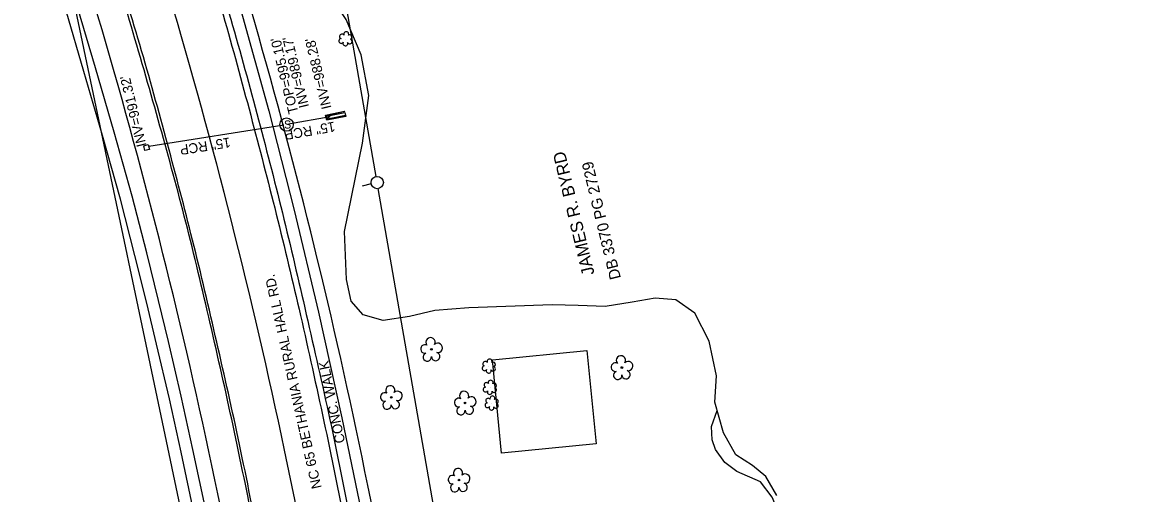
# Model space of a CAD drawing. Extents: x 1611576 to 1617186, y 899279 to 905462.
# Drawn here: x 1616538.9 to 1616993.3, y 902658.3 to 902848.6 of the extents above; entities that cross this region are included whole.
import ezdxf

# ---------------------------------------------------------------- set-up
doc = ezdxf.new("R2010")
doc.units = 0
for name, color, linetype in [('Default', 7, 'Continuous'), ('Exist Building', 7, 'Continuous'), ('Exist Horizontal Alignment', 7, 'Continuous'), ('Exist Property Deed Book Text', 7, 'Continuous'), ('Exist Property Owner Text', 7, 'Continuous'), ('Exist Right of Way Line', 7, 'Continuous'), ('Exist Roads Curbs', 7, 'Continuous'), ('Exist Roads EOP', 7, 'Continuous'), ('Exist Roads EOP Other', 7, 'Continuous'), ('Exist Roads EOP Other Text', 7, 'Continuous'), ('Exist Roads EOP Text', 7, 'Continuous'), ('Exist Roads EOT', 7, 'Continuous'), ('Exist Structure Minor Drop Inlet', 7, 'Continuous'), ('Exist Structure Minor Head and End Wall', 7, 'Continuous'), ('Exist Structure Minor Pipes RCP 15 Inch', 7, 'Continuous'), ('Exist Structure Minor Pipes RCP 15 Inch Invert', 7, 'Continuous'), ('Exist Structure Minor Pipes RCP 15 Inch Text', 7, 'Continuous'), ('Exist Structure Minor Storm Sewer Manhole CELL', 7, 'Continuous'), ('Exist Structure Minor Storm Sewer Manhole Top Elevation', 7, 'Continuous'), ('Exist Vegetation Hedge Row', 7, 'Continuous'), ('Exist Vegetation Shrub CELL', 7, 'Continuous'), ('Exist Vegetation Tree CELL', 7, 'Continuous'), ('Exist Vegetation Woods Line', 7, 'Continuous'), ('Prop OH Pow Lines', 7, 'Continuous')]:
    doc.layers.add(name, color=color, linetype=linetype)

# ---------------------------------------------------------------- blocks, each defined once
blk = doc.blocks.new('EXIST STRUCTURE MINOR STORM SEWER MANHOLE')
at = {"layer": 'Exist Structure Minor Storm Sewer Manhole CELL'}
blk.add_circle((0, 0), 0.0539, dxfattribs=at)
blk.add_text('S', height=0.065, dxfattribs=at).set_placement((-0.0206, -0.032))

msp = doc.modelspace()

# ---------------------------------------------------------------- linework, layer by layer
at = {"layer": 'Default'}
msp.add_line((1616679.58, 902783.35), (1616675.92, 902782.51), dxfattribs=at)
msp.add_circle((1616682.02, 902783.91), 2.5, dxfattribs=at)
at = {"layer": 'Exist Building'}
msp.add_lwpolyline([(1616766.61, 902716.05), (1616770.33, 902678.38), (1616732.23, 902674.63), (1616728.52, 902712.29)], close=True, dxfattribs=at)
at = {"layer": 'Exist Horizontal Alignment'}
msp.add_arc((1614325.74, 902186.35), 2370, 9.05, 18.23333, dxfattribs=at)
at = {"layer": 'Exist Right of Way Line'}
msp.add_line((1616010.65, 905462.23), (1616993.32, 900797.76), dxfattribs=at)
for radius, end in [(2400, 17.96643), (2340, 18.2273)]:
    msp.add_arc((1614325.74, 902186.35), radius, 9.05, end, dxfattribs=at)
at = {"layer": 'Exist Roads Curbs'}
msp.add_spline([(1616609.89, 902892.41), (1616622.17, 902852.43), (1616633.45, 902811.75), (1616643.74, 902771.73), (1616653.39, 902730.67), (1616662.94, 902688.03), (1616671.61, 902645.14)], degree=3, dxfattribs=at)
at = {"layer": 'Exist Roads EOP'}
for points in [[(1616664.02, 902435.24), (1616659.23, 902479.02), (1616653.86, 902521.19), (1616647.48, 902561.19), (1616640.05, 902603.13), (1616633.52, 902638.17), (1616624.95, 902680.56), (1616615.82, 902721.84), (1616606.01, 902763.05), (1616595.75, 902801.7), (1616584.26, 902841.93), (1616572.3, 902881.24), (1616564.26, 902906.37), (1616556.43, 902931.12), (1616543.99, 902967.9), (1616530.08, 903008.97), (1616517.05, 903047.39)], [(1616607.54, 902891.47), (1616619.8, 902851.65), (1616630.95, 902811.11), (1616641.26, 902771.18), (1616651.06, 902730.14), (1616660.51, 902687.43), (1616669.23, 902644.79), (1616673.27, 902623.83), (1616676.02, 902609.12), (1616683.43, 902567.11), (1616690.02, 902525.73), (1616695.57, 902482.82), (1616700.47, 902437.88)]]:
    msp.add_spline(points, degree=3, dxfattribs=at)
at = {"layer": 'Exist Roads EOP Other'}
for points in [[(1616614.65, 902893.86), (1616626.96, 902853.56), (1616638.24, 902812.83), (1616648.55, 902772.75), (1616658.26, 902731.61), (1616667.73, 902688.88), (1616676.31, 902647.23)], [(1616588.99, 902755.56), (1616583.12, 902778.42), (1616575.83, 902804.32), (1616568.31, 902830.2), (1616561.1, 902854.77), (1616553.97, 902877.13), (1616549.79, 902889.69), (1616545.16, 902888.13)], [(1616584.24, 902754.42), (1616578.41, 902777.13), (1616571.14, 902802.96), (1616563.63, 902828.8), (1616556.43, 902853.31), (1616549.33, 902875.6), (1616545.16, 902888.13)], [(1616669.29, 902810.95), (1616662.67, 902809.69), (1616662.27, 902810.92), (1616668.94, 902812.24), (1616669.29, 902810.95)], [(1616648.51, 902316.11), (1616647.25, 902342.52), (1616646.14, 902367.57), (1616644.85, 902387.63), (1616643.4, 902403.89), (1616641.55, 902422), (1616639.65, 902441.45), (1616637.53, 902461.4), (1616635.2, 902482.65), (1616632, 902508.68), (1616628.75, 902531.69), (1616625.18, 902554.85), (1616621.17, 902580.26), (1616616.86, 902604.66), (1616612.24, 902629.12), (1616608.13, 902650.05), (1616602.88, 902675.06), (1616598.15, 902696.53), (1616592.96, 902718.62), (1616589.01, 902735.14), (1616584.24, 902754.42)], [(1616653.39, 902316.3), (1616652.13, 902342.73), (1616651.02, 902367.82), (1616649.72, 902387.98), (1616648.26, 902404.34), (1616646.41, 902422.47), (1616644.51, 902441.92), (1616642.39, 902461.9), (1616640.05, 902483.2), (1616636.84, 902509.29), (1616633.58, 902532.38), (1616630.01, 902555.58), (1616625.98, 902581.04), (1616621.66, 902605.52), (1616617.03, 902630.01), (1616612.92, 902650.99), (1616607.66, 902676.06), (1616602.92, 902697.58), (1616597.72, 902719.72), (1616593.76, 902736.26), (1616588.99, 902755.56)]]:
    msp.add_lwpolyline(points, dxfattribs=at)
at = {"layer": 'Exist Roads EOT'}
msp.add_spline([(1616665.13, 902435.43), (1616660.48, 902479.08), (1616654.89, 902521.26), (1616648.51, 902561.33), (1616641.12, 902603.28), (1616634.46, 902638.28), (1616625.9, 902680.69), (1616616.67, 902721.99), (1616606.86, 902763.22), (1616596.71, 902801.99), (1616585.45, 902842.18), (1616573.19, 902881.5), (1616565.19, 902906.61), (1616557.25, 902931.31), (1616544.89, 902968.22), (1616530.94, 903009.35), (1616518.06, 903047.65)], degree=3, dxfattribs=at)
at = {"layer": 'Exist Structure Minor Drop Inlet'}
msp.add_lwpolyline([(1616590.07, 902797.3), (1616588.28, 902796.82), (1616587.76, 902798.76), (1616589.55, 902799.24)], close=True, dxfattribs=at)
at = {"layer": 'Exist Structure Minor Head and End Wall'}
msp.add_lwpolyline([(1616669.36, 902810.59), (1616661.68, 902809.13), (1616661.19, 902811.17), (1616668.87, 902812.75), (1616668.95, 902812.54), (1616661.48, 902810.88), (1616662, 902809.48), (1616669.32, 902810.85), (1616669.36, 902810.59)], dxfattribs=at)
at = {"layer": 'Exist Structure Minor Pipes RCP 15 Inch'}
for p, q in [((1616644.38, 902807.05), (1616589.89, 902798.47)), ((1616644.38, 902807.05), (1616589.89, 902798.47)), ((1616663.03, 902810.45), (1616646.24, 902807.53)), ((1616663.03, 902810.45), (1616646.24, 902807.53))]:
    msp.add_line(p, q, dxfattribs=at)
at = {"layer": 'Exist Vegetation Hedge Row'}
msp.add_lwpolyline([(1616844.72, 902649.14), (1616841.43, 902656.84), (1616836.76, 902662.96), (1616827.16, 902667.24), (1616822.29, 902670.83), (1616818.54, 902676.14), (1616817.17, 902680.02), (1616816.97, 902685.34), (1616819.21, 902691.86)], dxfattribs=at)
at = {"layer": 'Exist Vegetation Shrub CELL'}
for p, q in [((1616669.29, 902841.79), (1616669.29, 902841.79)), ((1616727.14, 902709.57), (1616727.14, 902709.57)), ((1616727.58, 902701.01), (1616727.58, 902701.01)), ((1616728.29, 902694.66), (1616728.29, 902694.66))]:
    msp.add_line(p, q, dxfattribs=at)
for centre, radius, start, end in [((1616667.81, 902842.92), 0.968, 35.8908, 245.4216), ((1616669.52, 902843.83), 0.99, 334.8391, 200.4717), ((1616670.96, 902842.66), 0.929, 284.4567, 126.0861), ((1616667.49, 902841.09), 0.955, 95.1099, 327.9534), ((1616669.16, 902840.11), 0.984, 151.2797, 21.387), ((1616670.92, 902840.86), 0.937, 204.9913, 73.4601), ((1616725.66, 902710.7), 0.968, 35.8908, 245.4216), ((1616727.37, 902711.61), 0.99, 334.8391, 200.4717), ((1616728.82, 902710.44), 0.929, 284.4567, 126.0861), ((1616725.34, 902708.87), 0.955, 95.1099, 327.9534), ((1616727.01, 902707.89), 0.984, 151.2797, 21.387), ((1616728.78, 902708.64), 0.937, 204.9913, 73.4601), ((1616726.1, 902702.14), 0.968, 35.8908, 245.4216), ((1616727.81, 902703.05), 0.99, 334.8391, 200.4717), ((1616729.25, 902701.88), 0.929, 284.4567, 126.0861), ((1616725.78, 902700.31), 0.955, 95.1099, 327.9534), ((1616727.45, 902699.33), 0.984, 151.2797, 21.387), ((1616728.51, 902696.7), 0.99, 334.8391, 200.4717), ((1616729.22, 902700.08), 0.937, 204.9913, 73.4601), ((1616726.49, 902693.96), 0.955, 95.1099, 327.9534), ((1616726.8, 902695.79), 0.968, 35.8908, 245.4216), ((1616728.16, 902692.98), 0.984, 151.2797, 21.387), ((1616729.92, 902693.73), 0.937, 204.9913, 73.4601), ((1616729.96, 902695.53), 0.929, 284.4567, 126.0861)]:
    msp.add_arc(centre, radius, start, end, dxfattribs=at)
at = {"layer": 'Exist Vegetation Tree CELL'}
for p, q in [((1616703.92, 902716.54), (1616703.92, 902716.54)), ((1616780.78, 902709.19), (1616780.78, 902709.19)), ((1616687.69, 902697.12), (1616687.69, 902697.12)), ((1616717.49, 902694.89), (1616717.49, 902694.89)), ((1616715.02, 902663.73), (1616715.02, 902663.73))]:
    msp.add_line(p, q, dxfattribs=at)
for centre in [(1616703.92, 902716.54), (1616780.78, 902709.19), (1616687.69, 902697.12), (1616717.49, 902694.89), (1616715.02, 902663.73)]:
    msp.add_circle(centre, 0.326, dxfattribs=at)
for centre, radius, start, end in [((1616703.53, 902719.41), 1.86, 330.1651, 219.7134), ((1616701.31, 902716.69), 1.73, 62.6636, 279.3457), ((1616706.47, 902717.13), 1.9, 257.1011, 134.1999), ((1616702.21, 902713.42), 1.69, 111.5671, 6.231), ((1616705.59, 902713.64), 1.7, 181.2822, 74.56), ((1616778.17, 902709.35), 1.73, 62.6636, 279.3457), ((1616780.39, 902712.06), 1.86, 330.1651, 219.7134), ((1616783.33, 902709.78), 1.9, 257.1011, 134.1999), ((1616779.07, 902706.07), 1.69, 111.5671, 6.231), ((1616782.45, 902706.29), 1.7, 181.2822, 74.56), ((1616687.3, 902700), 1.86, 330.1651, 219.7134), ((1616685.08, 902697.28), 1.73, 62.6636, 279.3457), ((1616690.23, 902697.71), 1.9, 257.1011, 134.1999), ((1616717.11, 902697.76), 1.86, 330.1651, 219.7134), ((1616720.04, 902695.47), 1.9, 257.1011, 134.1999), ((1616685.98, 902694), 1.69, 111.5671, 6.231), ((1616689.36, 902694.22), 1.7, 181.2822, 74.56), ((1616714.89, 902695.04), 1.73, 62.6636, 279.3457), ((1616715.79, 902691.76), 1.69, 111.5671, 6.231), ((1616719.17, 902691.99), 1.7, 181.2822, 74.56), ((1616712.42, 902663.89), 1.73, 62.6636, 279.3457), ((1616714.64, 902666.61), 1.86, 330.1651, 219.7134), ((1616717.57, 902664.32), 1.9, 257.1011, 134.1999), ((1616713.32, 902660.61), 1.69, 111.5671, 6.231), ((1616716.69, 902660.84), 1.7, 181.2822, 74.56)]:
    msp.add_arc(centre, radius, start, end, dxfattribs=at)
at = {"layer": 'Exist Vegetation Woods Line'}
for points in [[(1616668.84, 902764.14), (1616676.13, 902799.8), (1616678.62, 902819.06), (1616675.55, 902835.43), (1616669.55, 902849.77), (1616650.05, 902878.92), (1616647.54, 902886.56), (1616646.67, 902894.57), (1616648.67, 902902.57), (1616653.53, 902907.32), (1616659.81, 902910.93), (1616671.71, 902909.53), (1616681.45, 902908.58), (1616696.21, 902909.36), (1616708.59, 902912.5), (1616716.51, 902914.22), (1616725.21, 902914.81), (1616737.14, 902914.37), (1616745.55, 902915.12), (1616761.84, 902918.71), (1616771.16, 902920.71), (1616780.96, 902922.08), (1616785.68, 902921.01), (1616787.32, 902918.96)], [(1616843.34, 902657.52), (1616838.93, 902665.15), (1616833.52, 902669.66), (1616826.71, 902673.97), (1616821.77, 902682.78), (1616818.25, 902695.26), (1616818.97, 902705.86), (1616816.06, 902719.89), (1616810.16, 902731.09), (1616802.5, 902736.59), (1616794.15, 902737.24), (1616784.89, 902735.54), (1616774.05, 902733.84), (1616763.17, 902734.3), (1616752.61, 902734.48), (1616719.04, 902733.33), (1616705.29, 902732.25), (1616695.04, 902729.84), (1616684.36, 902728.2), (1616676.4, 902730.52), (1616671.49, 902735.94), (1616669.67, 902744.68), (1616668.84, 902764.14)]]:
    msp.add_lwpolyline(points, dxfattribs=at)
at = {"layer": 'Prop OH Pow Lines'}
for p, q in [((1616681.59, 902786.37), (1616657.41, 902925.2)), ((1616712.6, 902608.35), (1616682.45, 902781.44))]:
    msp.add_line(p, q, dxfattribs=at)

# ---------------------------------------------------------------- block references
at = {"layer": 'Exist Structure Minor Storm Sewer Manhole CELL', "xscale": 50, "yscale": 50}
msp.add_blockref('EXIST STRUCTURE MINOR STORM SEWER MANHOLE', (1616645.42, 902807.33), dxfattribs=at)

# ---------------------------------------------------------------- texts
at = {"layer": 'Exist Property Deed Book Text'}
msp.add_text('DB 3370 PG 2729', height=4.5, rotation=103.6417, dxfattribs=at).set_placement((1616780.42, 902745.33))
at = {"layer": 'Exist Property Owner Text'}
msp.add_text('JAMES R. BYRD', height=5, rotation=103.6417, dxfattribs=at).set_placement((1616769.78, 902747.06))
at = {"layer": 'Exist Roads EOP Other Text'}
msp.add_text('CONC. WALK', height=4, rotation=101.6421, dxfattribs=at).set_placement((1616669.1, 902679.02))
at = {"layer": 'Exist Roads EOP Text'}
msp.add_text('NC 65 BETHANIA RURAL HALL RD.', height=4, rotation=102.4863, dxfattribs=at).set_placement((1616659.6, 902660.68))
at = {"layer": 'Exist Structure Minor Pipes RCP 15 Inch Invert'}
for s, p in [("INV=989.17'", (1616654.54, 902814.6)), ("INV=988.28'", (1616663.6, 902814.07)), ("INV=991.32'", (1616588.96, 902798.85))]:
    msp.add_text(s, height=4, rotation=103.6417, dxfattribs=at).set_placement(p)
at = {"layer": 'Exist Structure Minor Pipes RCP 15 Inch Text'}
for rotation, p in [(189.8657, (1616664.66, 902808.53)), (188.9503, (1616622.47, 902802.16))]:
    msp.add_text('15" RCP', height=4, rotation=rotation, dxfattribs=at).set_placement(p)
at = {"layer": 'Exist Structure Minor Storm Sewer Manhole Top Elevation'}
msp.add_text("TOP=995.10'", height=4, rotation=103.6417, dxfattribs=at).set_placement((1616650.22, 902812.18))

doc.saveas('drawing.dxf')
